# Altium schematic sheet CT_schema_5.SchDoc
size 405 x 311 mm
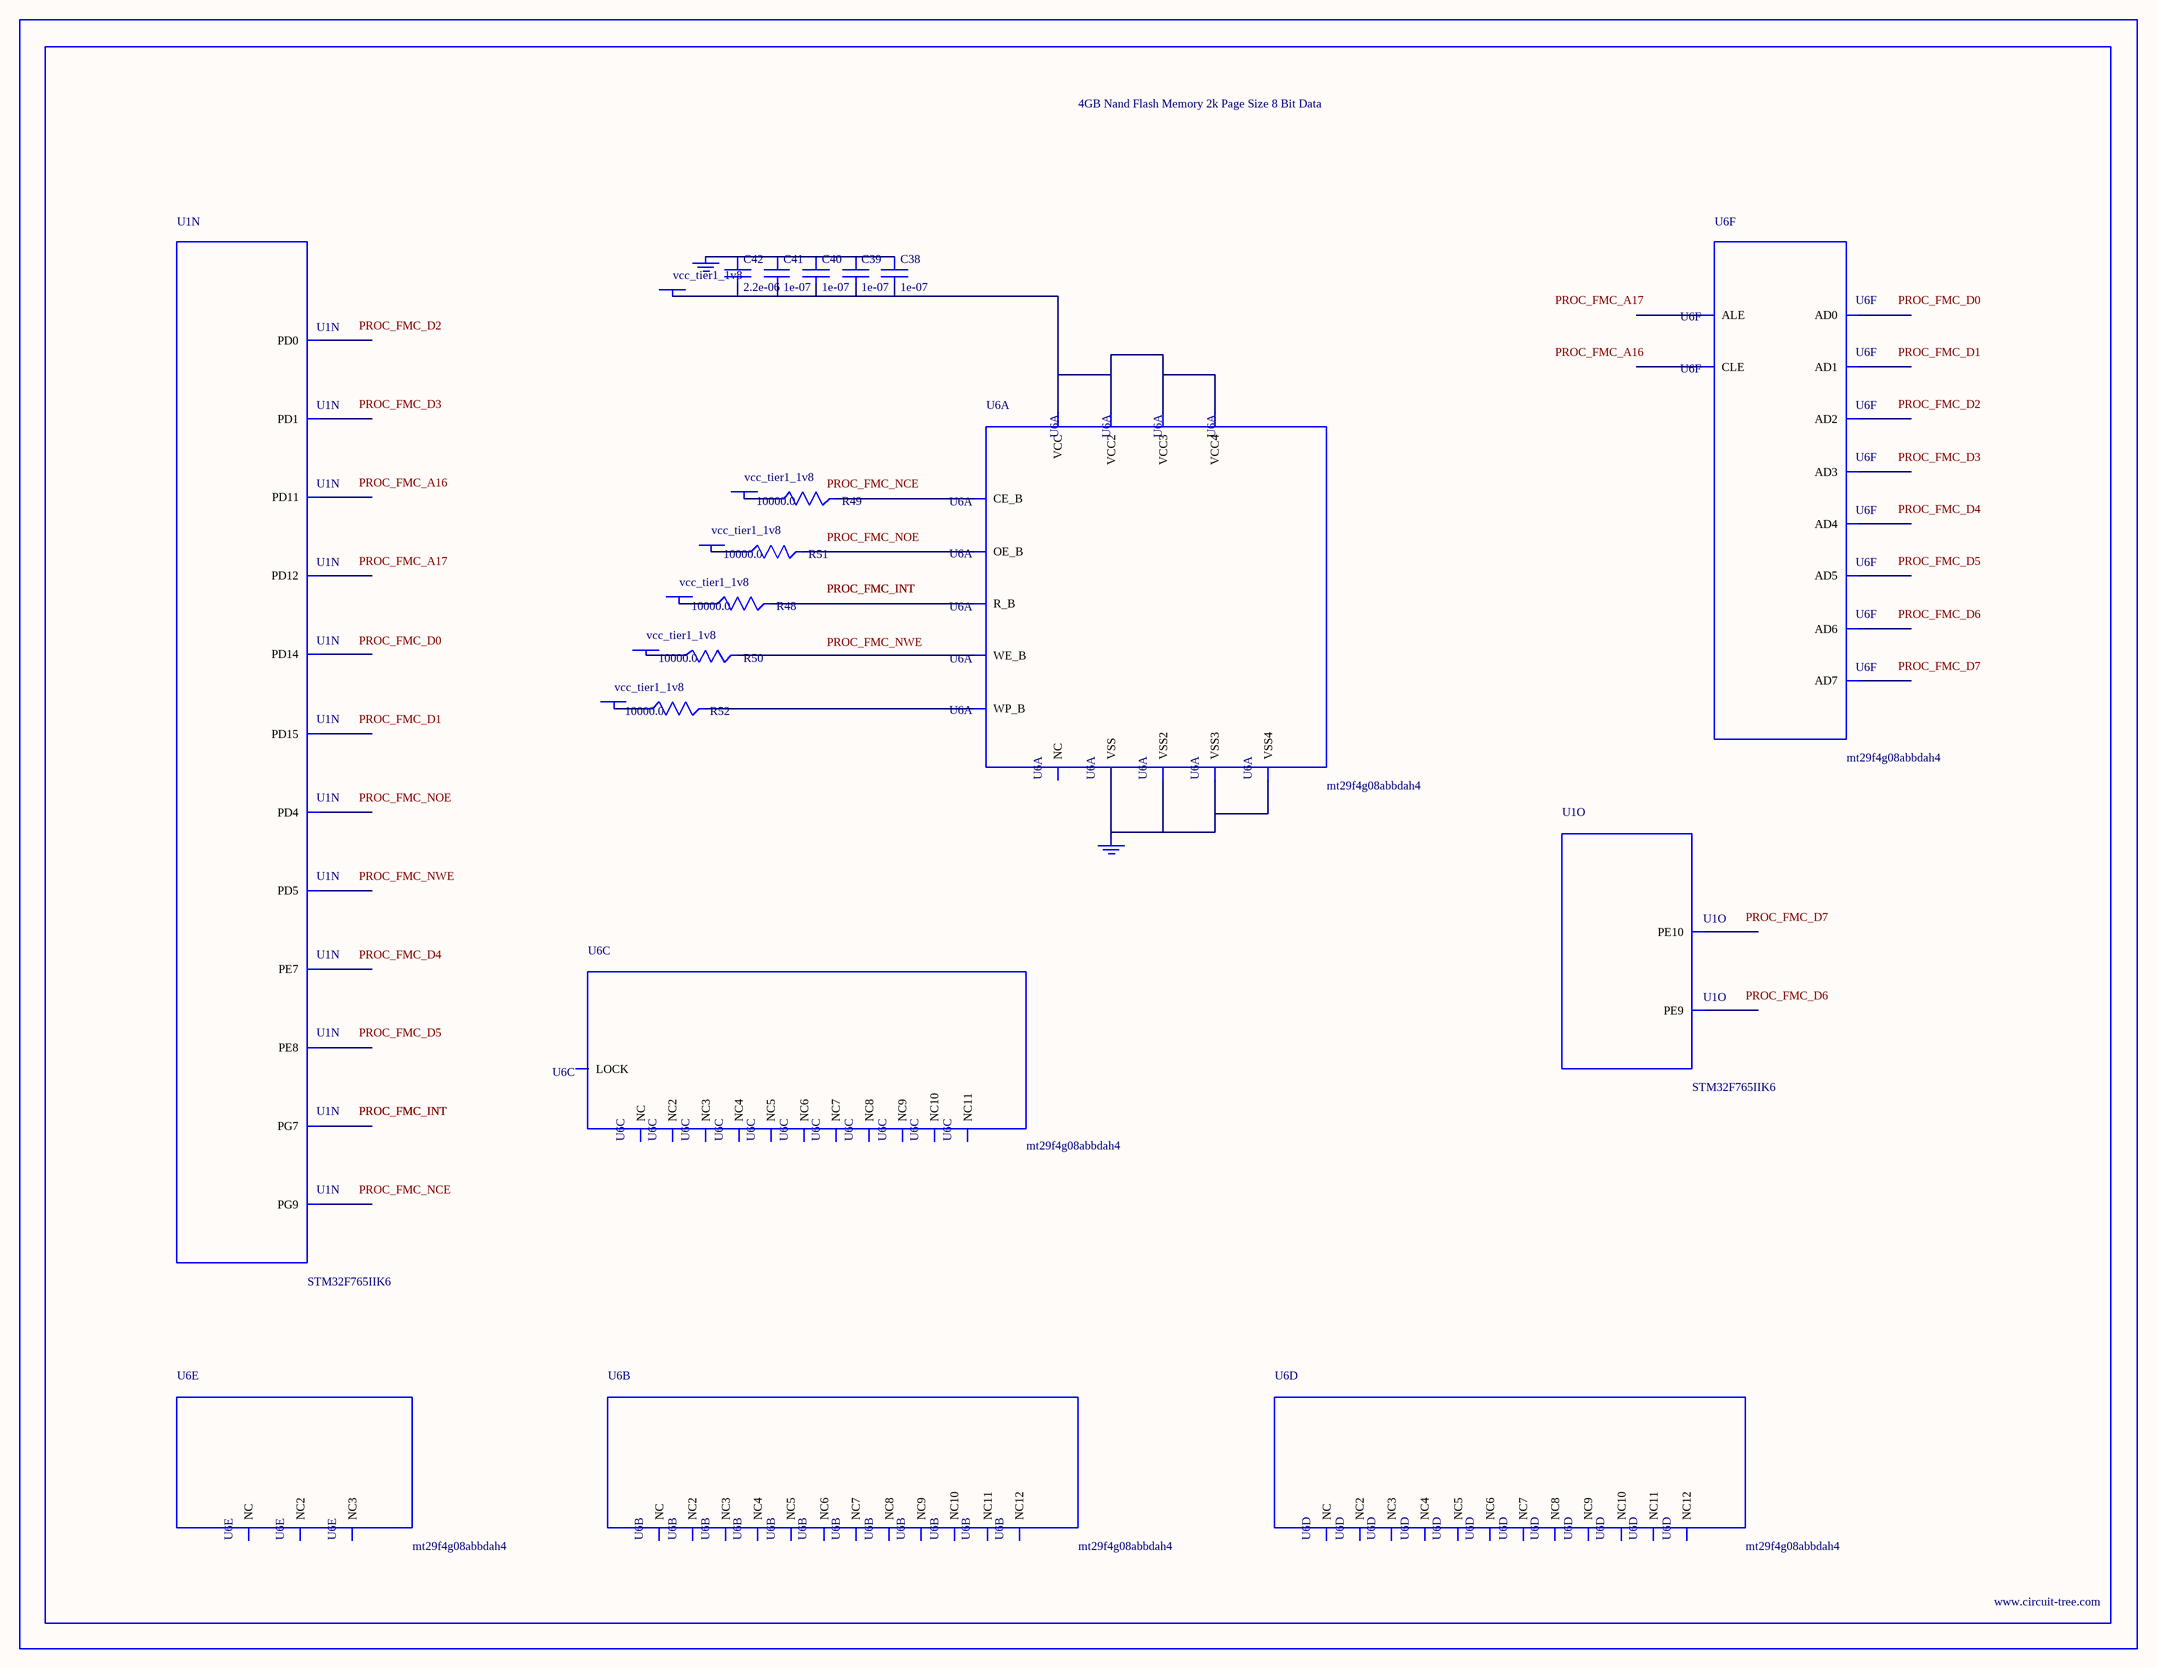
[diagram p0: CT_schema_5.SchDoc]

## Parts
BORDER4  (no value)
C38  1e-07  [C0402]
C39  1e-07  [C0402]
C40  1e-07  [C0402]
C41  1e-07  [C0402]
C42  2.2e-06  [C0603]
GND_INSTANCE_4_0  (no value)
GND_INSTANCE_4_1  (no value)
POWER_INSTANCE_4_0  vcc_tier1_1v8
POWER_INSTANCE_4_1  vcc_tier1_1v8
POWER_INSTANCE_4_2  vcc_tier1_1v8
POWER_INSTANCE_4_3  vcc_tier1_1v8
POWER_INSTANCE_4_4  vcc_tier1_1v8
POWER_INSTANCE_4_5  vcc_tier1_1v8
R48  10000.0  [R0603]
R49  10000.0  [R0603]
R50  10000.0  [R0603]
R51  10000.0  [R0603]
R52  10000.0  [R0603]
U1  STM32F765IIK6  [UFBGA176_25]  (parts N,O of 17)
U6  mt29f4g08abbdah4  [VFBGA-63]  (parts A,B,C,D,E,F of 6)

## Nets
NetC38_1: C38.1 C39.1 C40.1 C41.1 C42.1 GND_INSTANCE_4_0.0(GND)
NetC38_2: C38.2 C39.2 C40.2 C41.2 C42.2 POWER_INSTANCE_4_0.0(PWR) U6.D3(VCC) U6.G4(VCC2) U6.H8(VCC3) U6.J6(VCC4)
NetGND_INSTANCE_4_1_0: GND_INSTANCE_4_1.0(GND) U6.C5(VSS) U6.F7(VSS2) U6.K3(VSS3) U6.K8(VSS4)
NetPOWER_INSTANCE_4_1_0: POWER_INSTANCE_4_1.0(PWR) R48.1
NetPOWER_INSTANCE_4_2_0: POWER_INSTANCE_4_2.0(PWR) R49.1
NetPOWER_INSTANCE_4_3_0: POWER_INSTANCE_4_3.0(PWR) R50.1
NetPOWER_INSTANCE_4_4_0: POWER_INSTANCE_4_4.0(PWR) R51.1
NetPOWER_INSTANCE_4_5_0: POWER_INSTANCE_4_5.0(PWR) R52.1
NetR48_2: R48.2 U6.C8(R_B)
NetR49_2: R49.2 U6.C6(CE_B)
NetR50_2: R50.2 U6.C7(WE_B)
NetR51_2: R51.2 U6.D4(OE_B)
NetR52_2: R52.2 U6.C3(WP_B)

Not connected (* = marked no-connect by the designer): U1 B12(PD0) C10(PG9) C11(PD5) C12(PD1) D10(PD4) J14(PG7) L14(PD15) M14(PD14) N13(PD12) N14(PD11) P8(PE8) P9(PE9) R8(PE7) R9(PE10); U6 A1(NC) A2(NC3) A9(NC4) A10(NC2) B1(NC5) B9(NC7) B10(NC6) C4(ALE) D5(CLE) D6(NC8) D7(NC9) D8(NC10) E3(NC11) E4(NC12) E5(NC) E6(NC2) E7(NC3) E8(NC4) F3(NC5) F4(NC6) F5(NC7) F6(NC8) F8(NC9) G3(NC) G5(LOCK) G6(NC10) G7(NC11) G8(NC) H3(NC2) H4(AD0) H5(NC3) H6(NC4) H7(NC5) J3(NC6) J4(AD1) J5(NC7) J7(AD5) J8(AD7) K4(AD2) K5(AD3) K6(AD4) K7(AD6) L1(NC8) L2(NC10) L9(NC11) L10(NC9) M1(NC12) M2(NC2) M9(NC3) M10(NC)

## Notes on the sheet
- Labels drawn without touching a wire or pin: PROC_FMC_A16, PROC_FMC_A17, PROC_FMC_D0, PROC_FMC_D1, PROC_FMC_D2, PROC_FMC_D3, PROC_FMC_D4, PROC_FMC_D5, PROC_FMC_D6, PROC_FMC_D7, PROC_FMC_NCE, PROC_FMC_NOE, PROC_FMC_NWE

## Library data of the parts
BORDER4 = BORDER_PAGE4
C38-C41 = C0402C104K3RACTU
C42 = C0603C225K8RACTU
GND_INSTANCE_4_0 GND_INSTANCE_4_1 = GND
POWER_INSTANCE_4_0-POWER_INSTANCE_4_5 = PWR
R48-R52 = RC0603JR-0710KL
